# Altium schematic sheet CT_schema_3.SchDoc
size 461 x 297 mm
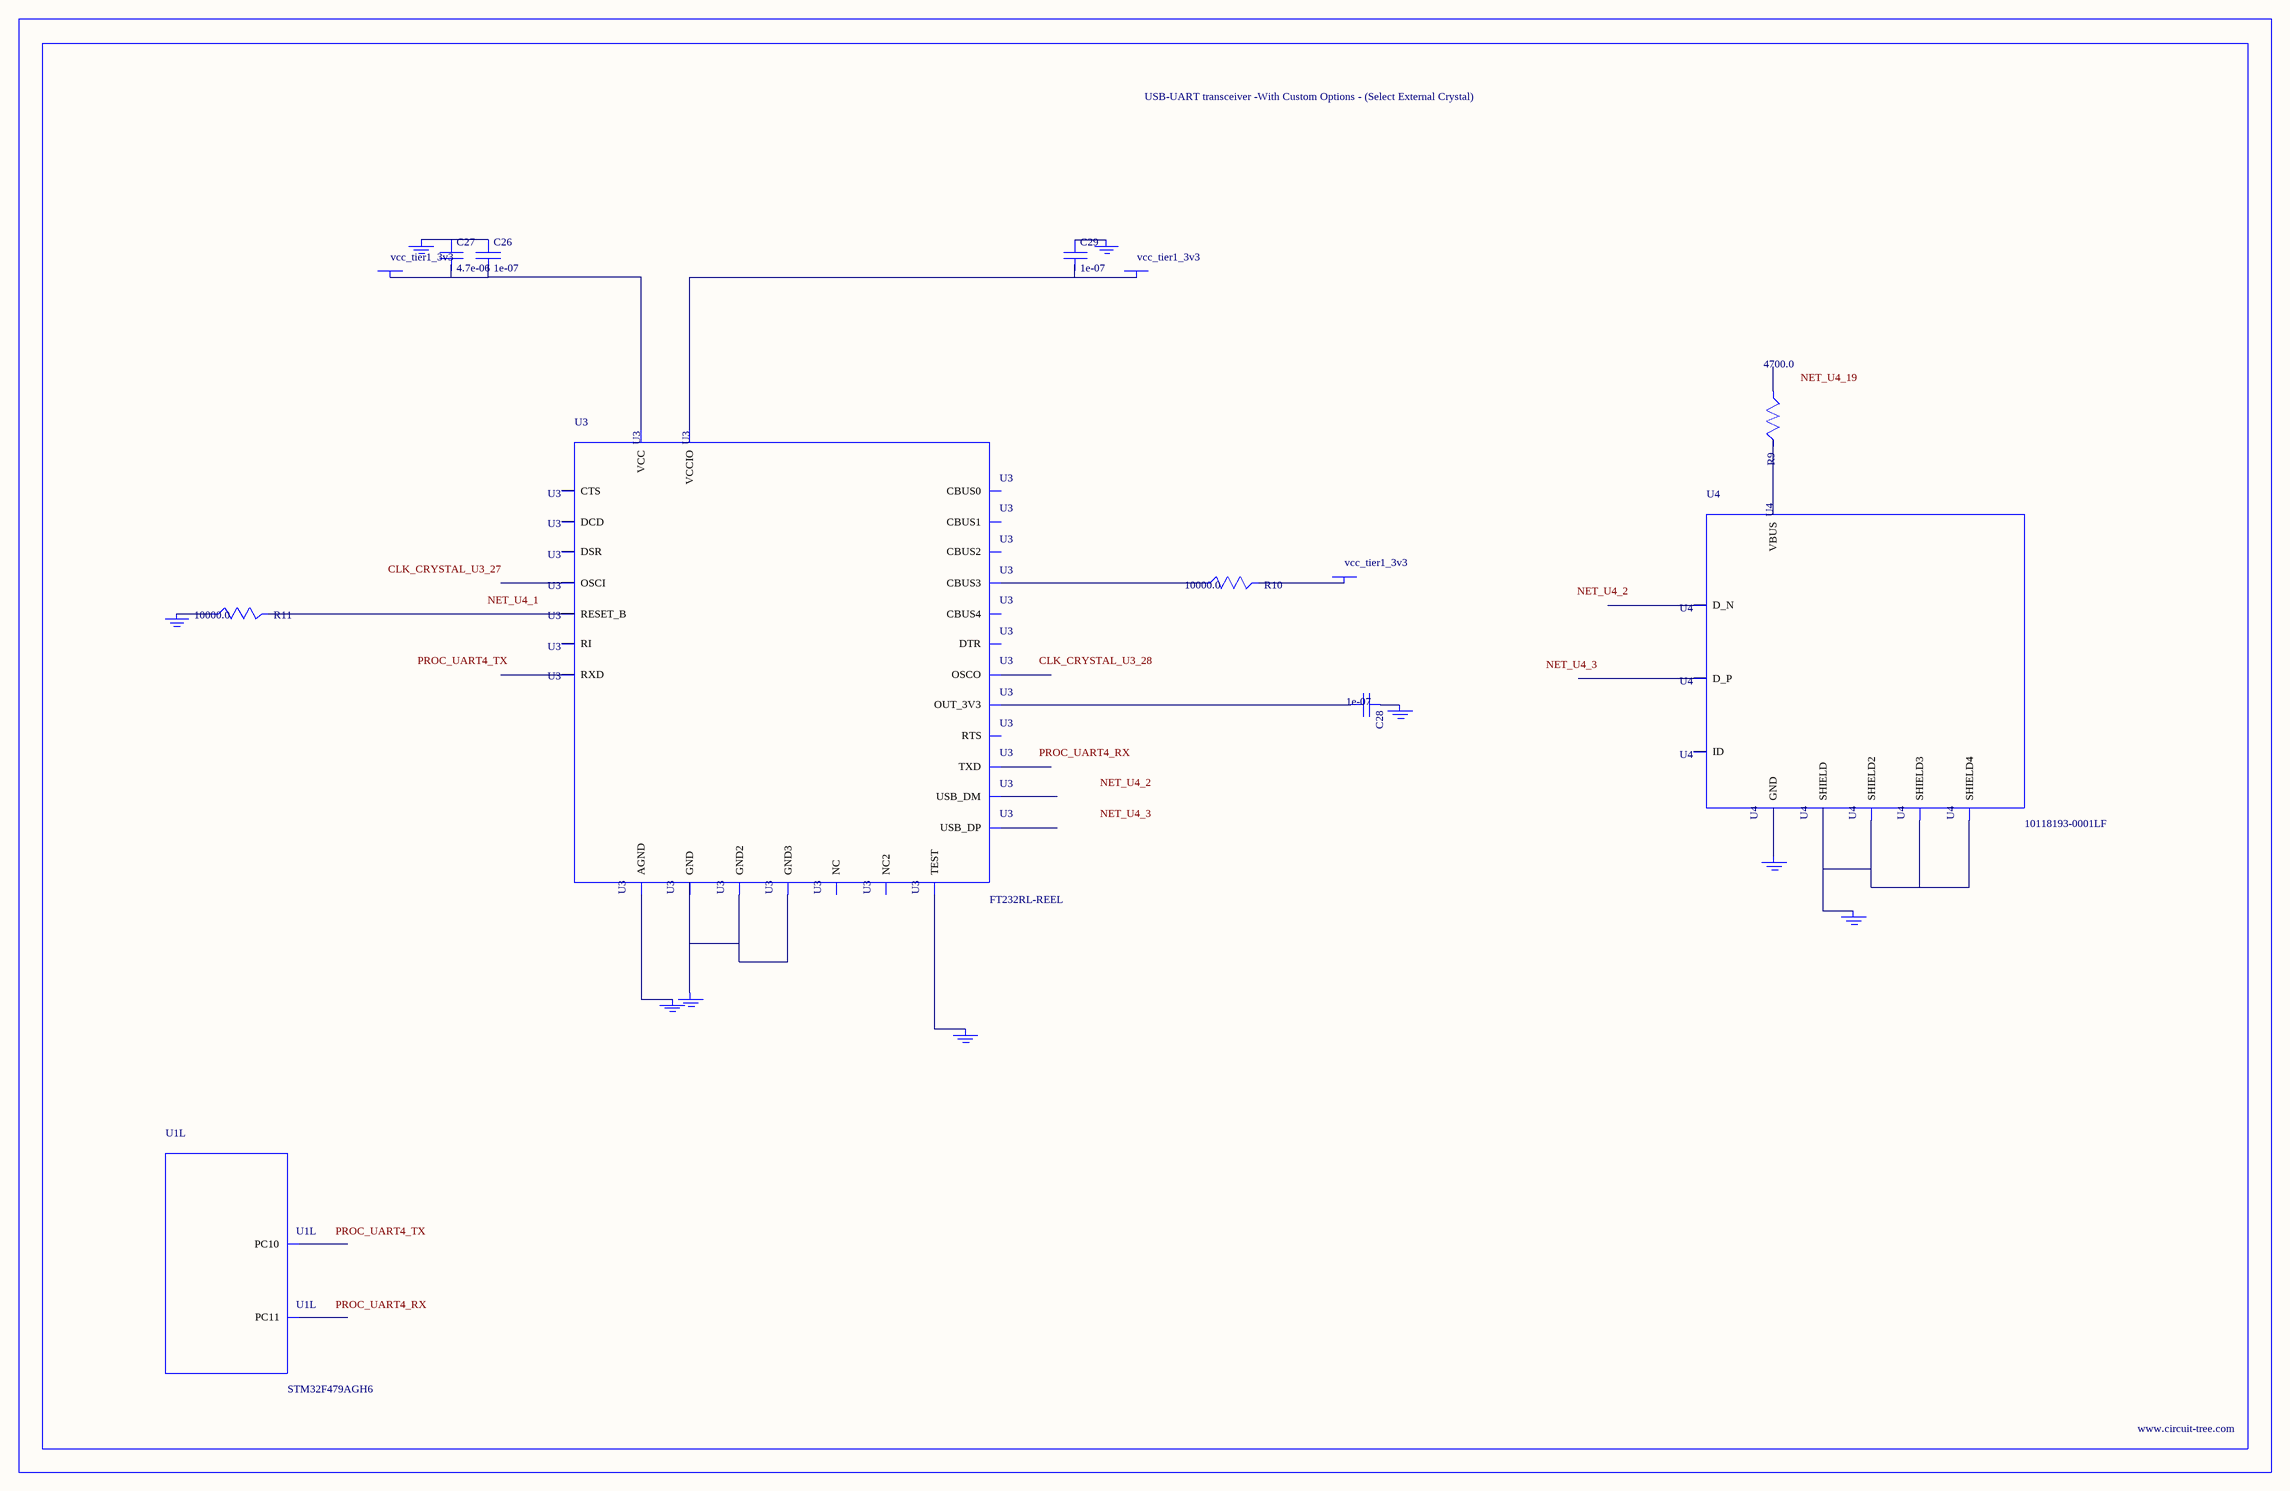
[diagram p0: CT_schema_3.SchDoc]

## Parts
BORDER2  (no value)
C26  1e-07  [C0402]
C27  4.7e-06  [C0805]
C28  1e-07  [C0402]
C29  1e-07  [C0402]
GND_INSTANCE_2_0  (no value)
GND_INSTANCE_2_1  (no value)
GND_INSTANCE_2_2  (no value)
GND_INSTANCE_2_3  (no value)
GND_INSTANCE_2_4  (no value)
GND_INSTANCE_2_5  (no value)
GND_INSTANCE_2_6  (no value)
GND_INSTANCE_2_7  (no value)
GND_INSTANCE_2_8  (no value)
POWER_INSTANCE_2_0  vcc_tier1_3v3
POWER_INSTANCE_2_1  vcc_tier1_3v3
POWER_INSTANCE_2_2  vcc_tier1_3v3
R9  4700.0  [R0603]
R10  10000.0  [R0603]
R11  10000.0  [R0603]
U1  STM32F479AGH6  [UFBGA169]  (part L of 12)
U3  FT232RL-REEL  [SSOP-28]
U4  10118193-0001LF  [FCI_10118193-0001LF]

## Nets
NetC26_1: C26.1 C27.1 GND_INSTANCE_2_3.0(GND)
NetC26_2: C26.2 C27.2 POWER_INSTANCE_2_2.0(PWR) U3.20(VCC)
NetC28_1: C28.1 GND_INSTANCE_2_1.0(GND)
NetC28_2: C28.2 U3.17(OUT_3V3)
NetC29_1: C29.1 GND_INSTANCE_2_0.0(GND)
NetC29_2: C29.2 POWER_INSTANCE_2_0.0(PWR) U3.4(VCCIO)
NetGND_INSTANCE_2_2_0: GND_INSTANCE_2_2.0(GND) R11.1
NetGND_INSTANCE_2_4_0: GND_INSTANCE_2_4.0(GND) U3.25(AGND)
NetGND_INSTANCE_2_5_0: GND_INSTANCE_2_5.0(GND) U3.26(TEST)
NetGND_INSTANCE_2_6_0: GND_INSTANCE_2_6.0(GND) U3.7(GND) U3.18(GND2) U3.21(GND3)
NetGND_INSTANCE_2_7_0: GND_INSTANCE_2_7.0(GND) U4.6(SHIELD) U4.7(SHIELD2) U4.8(SHIELD3) U4.9(SHIELD4)
NetGND_INSTANCE_2_8_0: GND_INSTANCE_2_8.0(GND) U4.5(GND)
NetPOWER_INSTANCE_2_1_0: POWER_INSTANCE_2_1.0(PWR) R10.2
NetR9_2: R9.2 U4.1(VBUS)
NetR10_1: R10.1 U3.14(CBUS3)
NetR11_2: R11.2 U3.19(RESET_B)

Not connected (* = marked no-connect by the designer): R9 1; U1 B9(PC11) C10(PC10); U3 1(TXD) 2(DTR) 3(RTS) 5(RXD) 6(RI) 8(NC) 9(DSR) 10(DCD) 11(CTS) 12(CBUS4) 13(CBUS2) 15(USB_DP) 16(USB_DM) 22(CBUS1) 23(CBUS0) 24(NC2) 27(OSCI) 28(OSCO); U4 2(D_N) 3(D_P) 4(ID)

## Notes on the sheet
- Labels drawn without touching a wire or pin: CLK_CRYSTAL_U3_27, CLK_CRYSTAL_U3_28, NET_U4_1, NET_U4_2, NET_U4_3, NET_U4_19, PROC_UART4_RX, PROC_UART4_TX

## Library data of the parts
BORDER2 = BORDER_PAGE2
C26 C28 C29 = C0402C104K3RACTU
C27 = C0805C475K4RACTU
GND_INSTANCE_2_0-GND_INSTANCE_2_8 = GND
POWER_INSTANCE_2_0-POWER_INSTANCE_2_2 = PWR
R9 = RC0603JR-074K7L
R10 R11 = RC0603JR-0710KL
